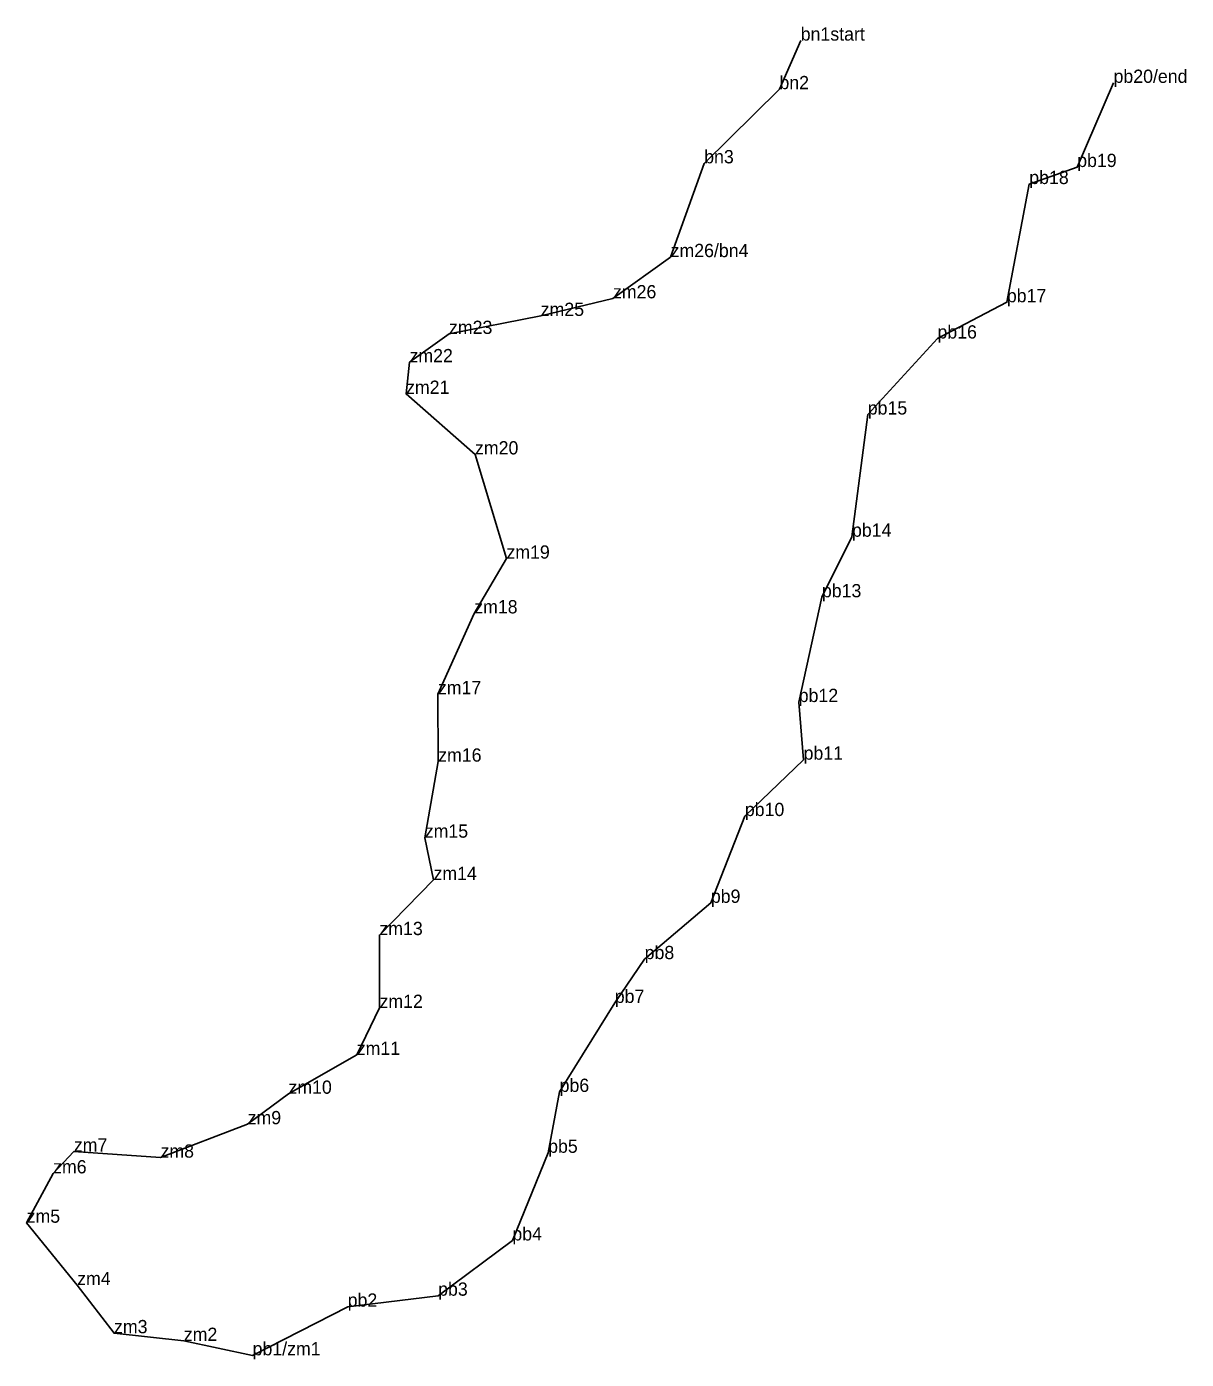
# Model space of a CAD drawing. Extents: x 2072529 to 2267990, y 436423 to 470008.
# Drawn here: x 2227991 to 2228516, y 438152 to 438755 of the extents above; entities that cross this region are included whole.
import ezdxf

# ---------------------------------------------------------------- set-up
doc = ezdxf.new("R2010")
doc.units = 0
doc.layers.add('Level 3', color=7, linetype='Continuous')
doc.layers.add('Old_Level_52', color=7, linetype='Continuous')

msp = doc.modelspace()

# ---------------------------------------------------------------- linework, layer by layer
at = {"layer": 'Level 3'}
for p, q in [((2228341.201, 438748.414), (2228341.201, 438748.414)), ((2228482.757, 438729.286), (2228482.757, 438729.286)), ((2228331.561, 438726.436), (2228331.561, 438726.436)), ((2228297.506, 438692.885), (2228297.506, 438692.885)), ((2228466.312, 438691.222), (2228466.312, 438691.222)), ((2228444.615, 438683.515), (2228444.615, 438683.515)), ((2228282.308, 438650.457), (2228282.308, 438650.457)), ((2228256.224, 438631.8), (2228256.224, 438631.8)), ((2228434.479, 438630.018), (2228434.479, 438630.018)), ((2228223.519, 438623.842), (2228223.519, 438623.842)), ((2228182.029, 438615.701), (2228182.029, 438615.701)), ((2228403.073, 438613.619), (2228403.073, 438613.619)), ((2228164.155, 438602.887), (2228164.155, 438602.887)), ((2228162.587, 438588.58), (2228162.587, 438588.58)), ((2228371.532, 438579.229), (2228371.532, 438579.229)), ((2228193.795, 438561.173), (2228193.795, 438561.173)), ((2228364.383, 438523.932), (2228364.383, 438523.932)), ((2228208.01, 438514.018), (2228208.01, 438514.018)), ((2228350.776, 438496.536), (2228350.776, 438496.536)), ((2228193.443, 438489.261), (2228193.443, 438489.261)), ((2228176.985, 438452.679), (2228176.985, 438452.679)), ((2228340.291, 438449.143), (2228340.291, 438449.143)), ((2228177.13, 438422.175), (2228177.13, 438422.175)), ((2228342.484, 438423.059), (2228342.484, 438423.059)), ((2228315.91, 438397.552), (2228315.91, 438397.552)), ((2228171.061, 438387.766), (2228171.061, 438387.766)), ((2228175.011, 438368.638), (2228175.011, 438368.638)), ((2228300.528, 438358.282), (2228300.528, 438358.282)), ((2228150.53, 438343.699), (2228150.53, 438343.699)), ((2228270.571, 438332.81), (2228270.571, 438332.81)), ((2228150.576, 438310.739), (2228150.576, 438310.739)), ((2228257.038, 438312.994), (2228257.038, 438312.994)), ((2228140.275, 438289.474), (2228140.275, 438289.474)), ((2228109.37, 438271.907), (2228109.37, 438271.907)), ((2228232.082, 438272.738), (2228232.082, 438272.738)), ((2228090.907, 438258.113), (2228090.907, 438258.113)), ((2228012.247, 438245.718), (2228012.247, 438245.718)), ((2228226.893, 438245.183), (2228226.893, 438245.183)), ((2228051.466, 438242.995), (2228051.466, 438242.995)), ((2228002.86, 438235.889), (2228002.86, 438235.889)), ((2227990.896, 438213.539), (2227990.896, 438213.539)), ((2228210.707, 438205.52), (2228210.707, 438205.52)), ((2228013.761, 438185.318), (2228013.761, 438185.318)), ((2228177.112, 438180.533), (2228177.112, 438180.533)), ((2228136.174, 438175.566), (2228136.174, 438175.566)), ((2228030.438, 438163.553), (2228030.438, 438163.553)), ((2228062.02, 438160.075), (2228062.02, 438160.075)), ((2228093.157, 438153.549), (2228093.157, 438153.549))]:
    msp.add_line(p, q, dxfattribs=at)
at = {"layer": 'Old_Level_52'}
msp.add_lwpolyline([(2228341.201, 438748.414), (2228331.561, 438726.436), (2228297.506, 438692.885), (2228282.308, 438650.457), (2228256.224, 438631.8), (2228223.519, 438623.842), (2228182.029, 438615.701), (2228164.155, 438602.887), (2228162.587, 438588.58), (2228193.795, 438561.173), (2228208.01, 438514.018), (2228193.443, 438489.261), (2228176.985, 438452.679), (2228177.13, 438422.175), (2228171.061, 438387.766), (2228175.011, 438368.638), (2228150.53, 438343.699), (2228150.576, 438310.739), (2228140.275, 438289.474), (2228109.37, 438271.907), (2228090.907, 438258.113), (2228051.466, 438242.995), (2228012.247, 438245.718), (2228002.86, 438235.889), (2227990.896, 438213.539), (2228013.761, 438185.318), (2228030.438, 438163.553), (2228062.02, 438160.075), (2228093.157, 438153.549), (2228136.174, 438175.566), (2228177.112, 438180.533), (2228210.707, 438205.52), (2228226.893, 438245.183), (2228232.082, 438272.738), (2228257.038, 438312.994), (2228270.571, 438332.81), (2228300.528, 438358.282), (2228315.91, 438397.552), (2228342.484, 438423.059), (2228340.291, 438449.143), (2228350.776, 438496.536), (2228364.383, 438523.932), (2228371.532, 438579.229), (2228403.073, 438613.619), (2228434.479, 438630.018), (2228444.615, 438683.515), (2228466.312, 438691.222), (2228482.757, 438729.286)], dxfattribs=at)

# ---------------------------------------------------------------- texts
for s, p in [('bn1start', (2228341.201, 438748.414)), ('bn2', (2228331.561, 438726.436)), ('pb20/end', (2228482.757, 438729.286)), ('bn3', (2228297.506, 438692.885)), ('pb19', (2228466.312, 438691.222)), ('pb18', (2228444.615, 438683.515)), ('zm26/bn4', (2228282.308, 438650.457)), ('zm26', (2228256.224, 438631.8)), ('pb17', (2228434.479, 438630.018)), ('zm25', (2228223.519, 438623.842)), ('zm23', (2228182.029, 438615.701)), ('pb16', (2228403.073, 438613.619)), ('zm22', (2228164.155, 438602.887)), ('zm21', (2228162.587, 438588.58)), ('pb15', (2228371.532, 438579.229)), ('zm20', (2228193.795, 438561.173)), ('pb14', (2228364.383, 438523.932)), ('zm19', (2228208.01, 438514.018)), ('pb13', (2228350.776, 438496.536)), ('zm18', (2228193.443, 438489.261)), ('zm17', (2228176.985, 438452.679)), ('pb12', (2228340.291, 438449.143)), ('zm16', (2228177.13, 438422.175)), ('pb11', (2228342.484, 438423.059)), ('pb10', (2228315.91, 438397.552)), ('zm15', (2228171.061, 438387.766)), ('zm14', (2228175.011, 438368.638)), ('pb9', (2228300.528, 438358.282)), ('zm13', (2228150.53, 438343.699)), ('pb8', (2228270.571, 438332.81)), ('zm12', (2228150.576, 438310.739)), ('pb7', (2228257.038, 438312.994)), ('zm11', (2228140.275, 438289.474)), ('zm10', (2228109.37, 438271.907)), ('pb6', (2228232.082, 438272.738)), ('zm9', (2228090.907, 438258.113)), ('zm7', (2228012.247, 438245.718)), ('pb5', (2228226.893, 438245.183)), ('zm8', (2228051.466, 438242.995)), ('zm6', (2228002.86, 438235.889)), ('zm5', (2227990.896, 438213.539)), ('pb4', (2228210.707, 438205.52)), ('zm4', (2228013.761, 438185.318)), ('pb3', (2228177.112, 438180.533)), ('pb2', (2228136.174, 438175.566)), ('zm3', (2228030.438, 438163.553)), ('zm2', (2228062.02, 438160.075)), ('pb1/zm1', (2228093.157, 438153.549))]:
    msp.add_text(s, height=6).set_placement(p)

doc.saveas('drawing.dxf')
